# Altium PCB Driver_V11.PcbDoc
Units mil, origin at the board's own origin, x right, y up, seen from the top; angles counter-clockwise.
Board outline 3267.72 x 2755.91 mil, 2 copper layers (TopLayer, BottomLayer); 59 components, 38 nets, 175 pads, 130 vias.
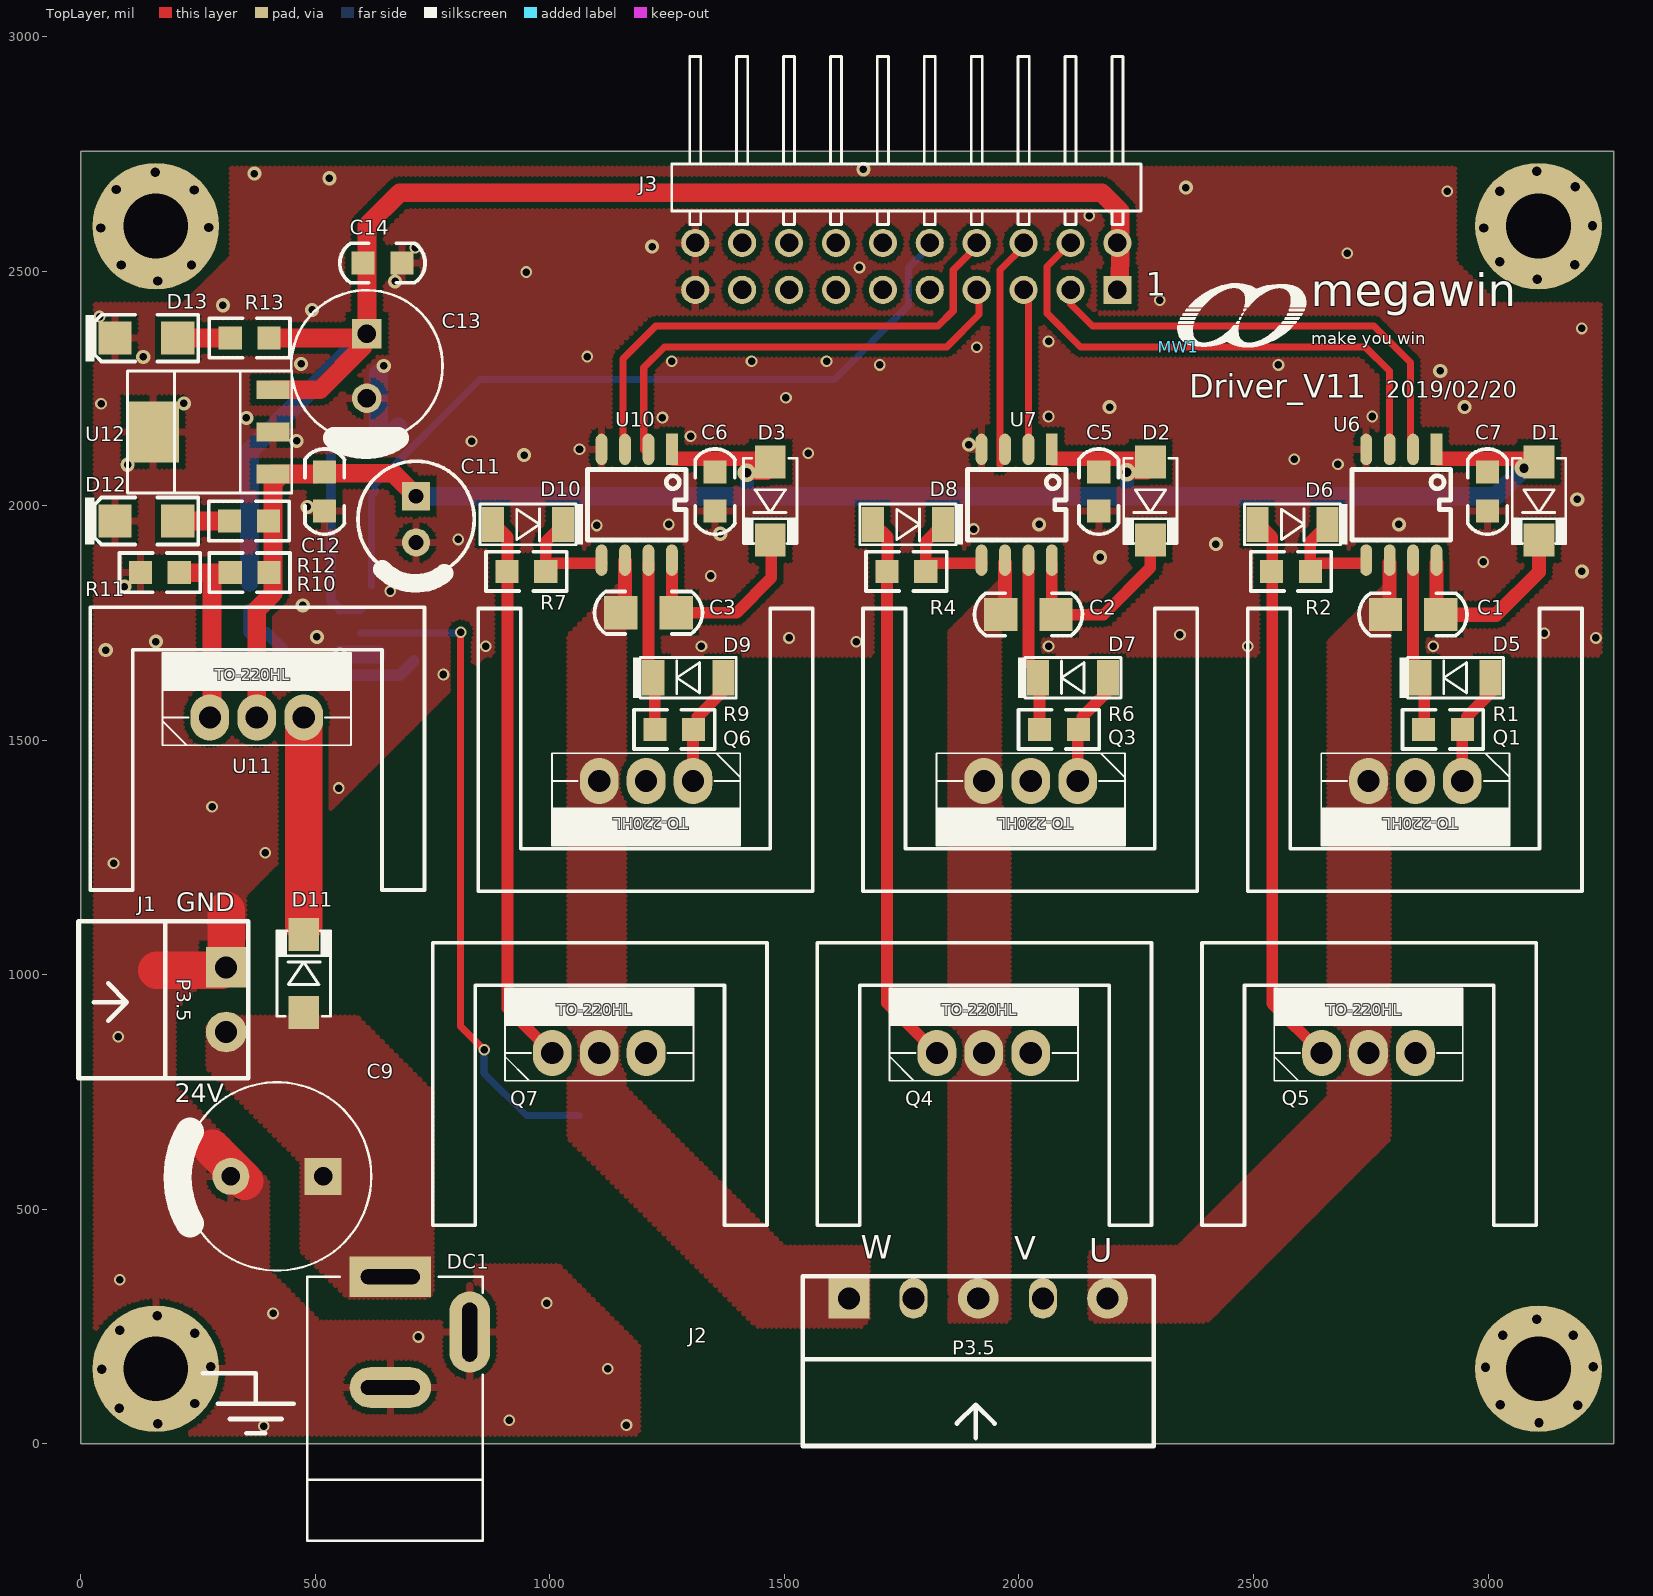
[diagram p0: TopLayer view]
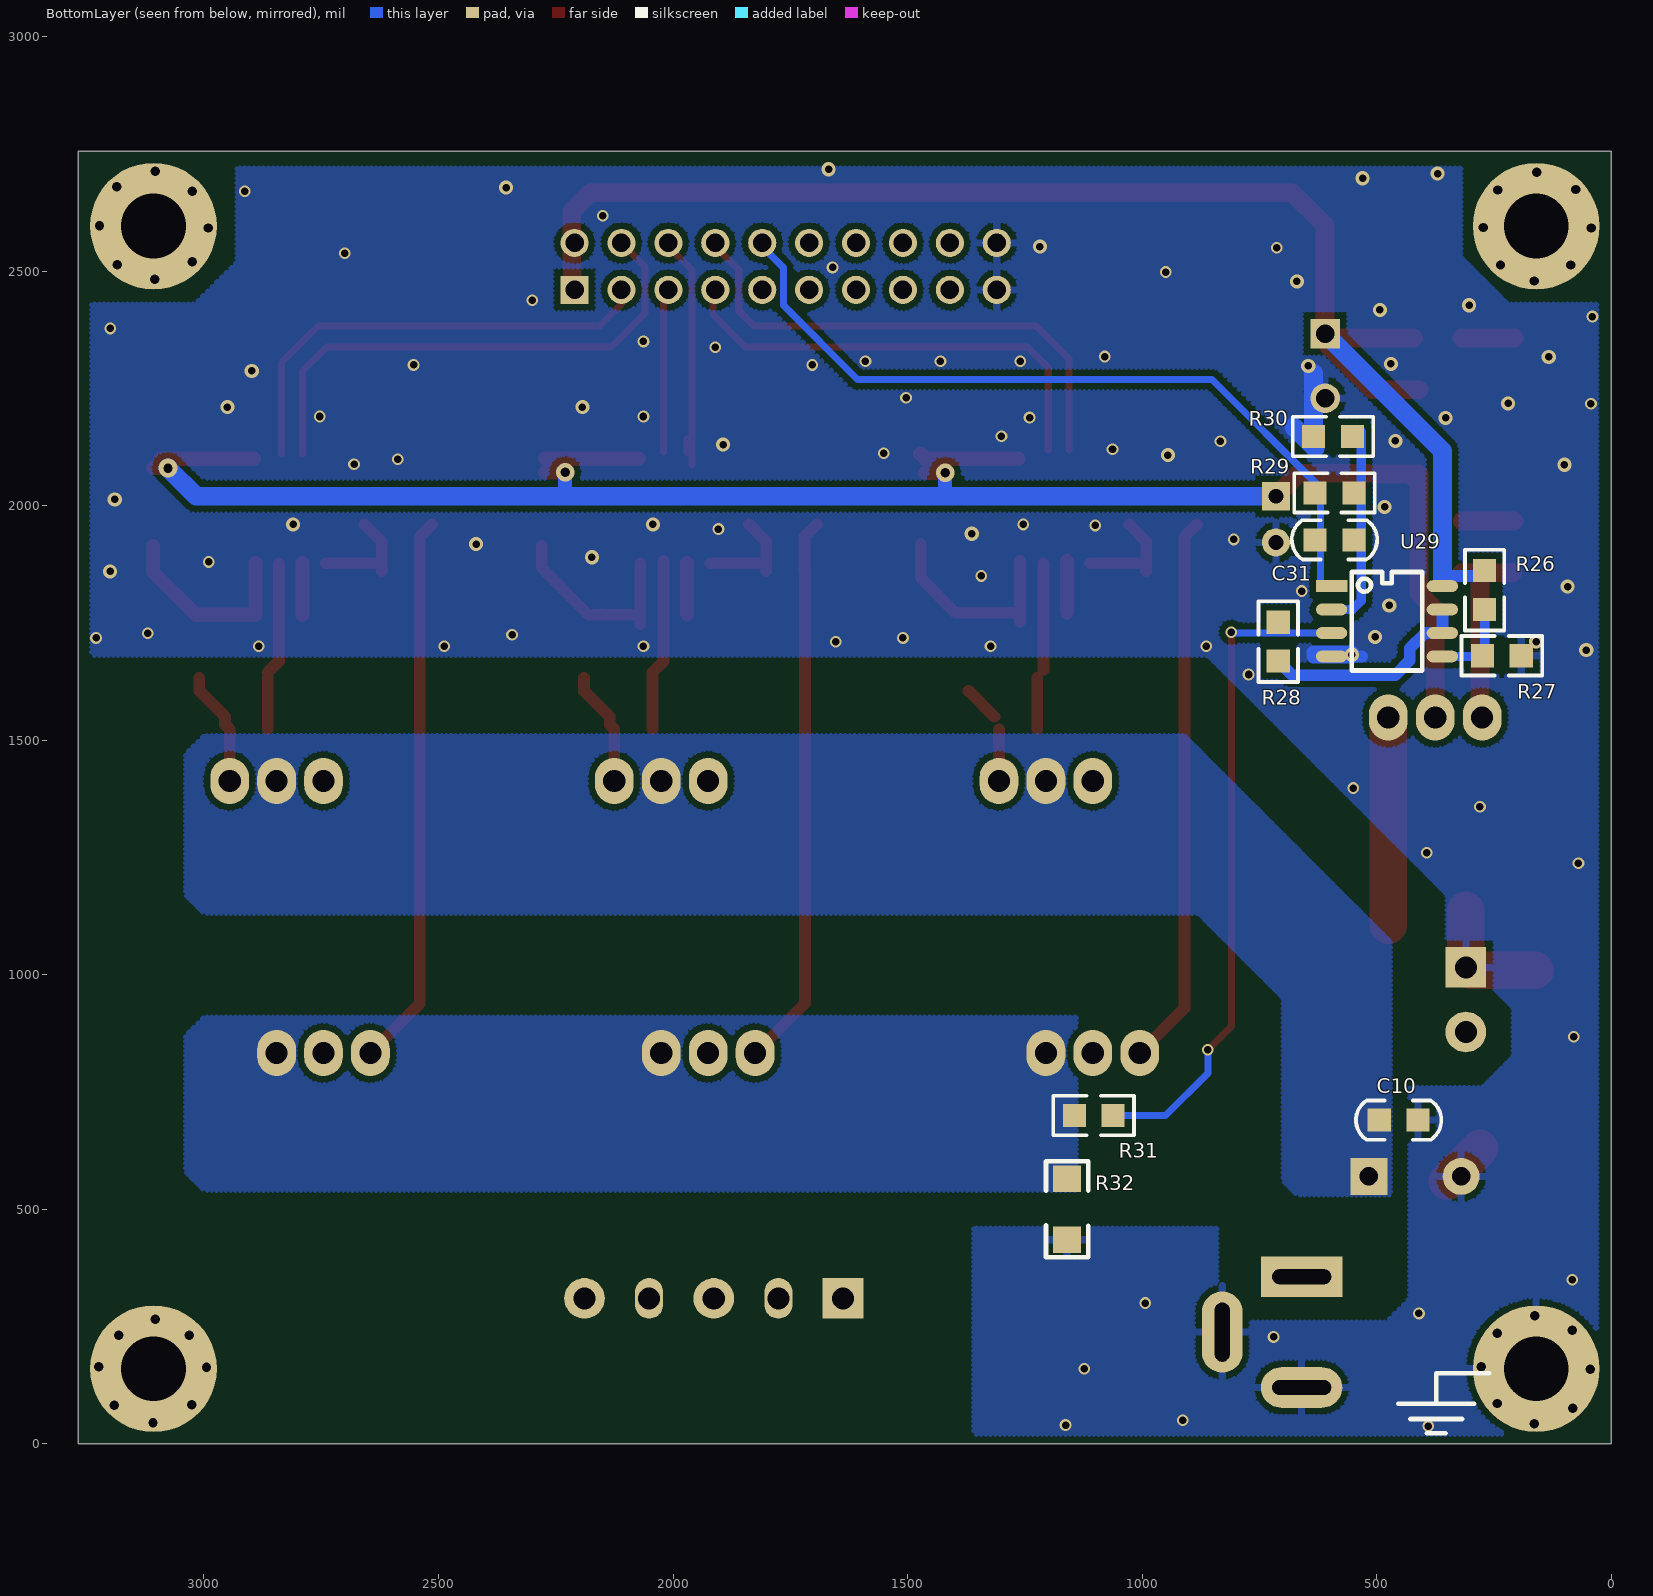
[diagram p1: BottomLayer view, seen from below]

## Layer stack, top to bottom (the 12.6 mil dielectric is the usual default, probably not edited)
TopLayer: signal copper 1.4
Dielectric: dielectric 12.6, FR-4, Dk 4.8
BottomLayer: signal copper 1.4

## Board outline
0,0 0,2755.91 3267.72,2755.91 3267.72,0

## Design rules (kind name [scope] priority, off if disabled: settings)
Clearance 20 [All] p1 off: gap=20
Clearance 13 [All] p2: gap=13
Clearance 6 [All] p3: gap=6
FabricationTestPointUsage TestPointUsage [All] p1: valid=0 allowmultiple=FALSE
FabricationTestpoint Testpoint [All] p1: side=3 testpointundercomponent=TRUE minsize=40 maxsize=100 preferedsize=60 minholesize=20 maxholesize=40 preferedholesize=32 testpointgrid=1 allowsidetop=TRUE allowsidebottom=TRUE usegrid=TRUE gridtolerance=0.01
HoleSize [All] p1: absolutevalues=TRUE maxlimit=500 minlimit=1 maxpercent=80.000 minpercent=20.000
PolygonConnect PWR [InNetClass('PWR')] p1: connectstyle=Direct reliefconductorwidth=10 reliefentries=4 polygonreliefangle="90 Angle"
PolygonConnect VIA [isvia] p2: connectstyle=Direct reliefconductorwidth=10 reliefentries=4 polygonreliefangle="90 Angle"
PolygonConnect PolygonConnect_1 [All] p3: connectstyle=Relief reliefconductorwidth=15 reliefentries=4 polygonreliefangle="90 Angle"
RoutingPriority [All] p1: routingpriority=4
RoutingVias [All] p1: holewidth=16 width=25 viastyle="Through Hole" minholewidth=16 minwidth=24 maxholewidth=28 maxwidth=50
SilkscreenOverComponentPads [All] p1: minsilkscreentomaskgap=10
SolderMaskExpansion [All] p1: expansion=4
Width [All] p1: maxlimit=100 minlimit=8 preferedwidth=10
23 further rules are at their usual default settings.

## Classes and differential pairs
net class pwr: 15V DC+ ICURRENT U V V0 VDD5V W

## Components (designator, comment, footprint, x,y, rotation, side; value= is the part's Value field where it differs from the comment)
C1 "10UF" 1206C 2840.26,1768.15 r180 top
C2 "10UF" 1206C 2020.26,1768.15 r180 top
C3 "10UF" 1206C 1210.26,1771.87 r180 top
C5 "104" 0805C 2170.26,2030 r270 top
C6 "104" 0805C 1352.32,2030 r270 top
C7 "104" 0805C 2998.7,2030 r270 top
C9 "220uF/63V" CEC102P050 418.42,570 r180 top
C10 "0.1u" 0805C 453.26,690 r180 bottom
C11 "47uF/50V" CEC063P025 715,1970.79 r270 top
C12 "0.1u" 0805C 520,2030 r270 top
C13 "220uF/35V" CEC082P035 610,2297.83 r270 top locked
C14 "0.1u" 0805C 643.26,2517.15 r0 top
C31 "2.7n" 0805C 590,1927.15 r0 bottom
D1 "ES1A/SM" DIODE_SMA 3108.7,2010 r270 top
D2 "ES1A/SM" DIODE_SMA 2280.26,2010 r270 top
D3 "ES1A/SM" DIODE_SMA 1470,2010 r270 top
D5 "1N4148" D4148_SMD 2930.46,1633.15 r180 top
D6 "1N4148" D4148_SMD 2583.26,1960 r0 top
D7 "1N4148" D4148_SMD 2115.26,1633.15 r180 top
D8 "1N4148" D4148_SMD 1763.26,1960 r0 top
D9 "1N4148" D4148_SMD 1295.26,1633.15 r180 top
D10 "1N4148" D4148_SMD 953.26,1960 r0 top
D11 "M4" DIODE_SMA 475.26,1002.57 r90 top
D12 "1206" 1206D 140,1967.15 r180 top
D13 "1206" 1206D 140,2357.15 r180 top
DC1 "DC JACK" JACK_DC_0 671.5,241.83 r90 top
J1 "24V / CON2" PW2P3.5_90 310,1015.62 r270 top
J2 "p3.5" PW5P3.5_90 1637.67,310 r0 top
J3 "CON20A" PS10X2P254_90 2210,2460 r180 top locked
MW1 "" MEGAWIN_3.4 2340,2337.83 r0 top
Q1 "IRF520N/TO" TO220HL18X15.3 2945.26,1413.15 r180 top locked
Q3 "IRF520N/TO" TO220HL18X15.3 2125.26,1413.15 r180 top locked
Q4 "IRF520N/TO" TO220HL18X15.3 1825.26,833.15 r0 top locked
Q5 "IRF520N/TO" TO220HL18X15.3 2645.26,833.15 r0 top locked
Q6 "IRF520N/TO" TO220HL18X15.3 1305.26,1413.15 r180 top locked
Q7 "IRF520N/TO" TO220HL18X15.3 1005.26,833.15 r0 top locked
R1 "33" 0805R 2903.92,1523.15 r0 top
R2 "33" 0805R 2580,1860 r180 top
R4 "33" 0805R 1760,1860 r180 top
R6 "33" 0805R 2085.26,1523.15 r0 top
R7 "33" 0805R 950,1860 r180 top
R9 "33" 0805R 1265.26,1523.15 r0 top
R10 "RESISTOR" 0805R 360,1857.15 r180 top
R11 "RESISTOR" 0805R 168.66,1857.15 r180 top
R12 "1K" 0805R 358.66,1967.15 r180 top
R13 "1K" 0805R 360,2357.15 r180 top
R26 "8.2K" 0805R 270,1820 r270 bottom
R27 "1.13K" 0805R 233.26,1680 r180 bottom
R28 "25.5k" 0805R 710,1710 r90 bottom
R29 "25.5k" 0805R 590,2027.15 r0 bottom
R30 "1.0K" 0805R 593.26,2147.15 r0 bottom
R31 "1.0K" 0805R 1103.26,700 r180 bottom
R32 "0.02  (1206)" 1206R 1160,500 r270 bottom
U6 "IR2101S" SO8_150P127 2890.26,2120 r270 top
U7 "IR2101S" SO8_150P127 2070.26,2120 r270 top
U10 "IR2101S" SO8_150P127 1260.26,2120 r270 top
U11 "LM317/TO" TO220HL18X15.3 275.26,1548.15 r0 top locked
U12 "LM78L05  (SOT223)" sot223 410,2067.15 r90 top
U29 "LM358" SO8_150P127 596.22,1828.49 r180 bottom

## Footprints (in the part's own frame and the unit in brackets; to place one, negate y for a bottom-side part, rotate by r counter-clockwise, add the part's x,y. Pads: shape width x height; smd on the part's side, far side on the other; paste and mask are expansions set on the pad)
0805C [mm]
  rect 1.25x1.25 smd: 1(-1.05,0) 2(1.05,0)
  silkscreen extent -2.31,-1.07 2.31,1.07
0805R [mm]
  rect 1.25x1.25 smd: 1(-1.05,0) 2(1.05,0)
  silkscreen extent -2.18,-1.07 2.18,1.07
1206C [mm]
  rect 1.8x1.8 smd: 1(-1.5,0) 2(1.5,0)
  silkscreen extent -2.92,-1.15 2.92,1.16
1206D [mm]
  rect 1.8x1.8 smd: 1(-1.7,0) 2(1.7,0)
  silkscreen extent -2.8,-1.27 3.31,1.28
1206R [mm]
  rect 1.45x1.524 smd: 1(-1.65,0) 2(1.65,0)
  silkscreen extent -2.6,-1.14 2.6,1.14
CEC063P025 [mil]
  rect 60x60 hole 31.5: 1(-49.21,0)
  round 60 hole 31.5: 2(49.21,0)
  silkscreen extent -124,-124 137,124
CEC082P035 [mm]
  rect 1.6x1.6 hole 1: 1(-1.75,0)
  round 1.6 hole 1: 2(1.75,0)
  silkscreen extent -4.1,-4.1 4.45,4.1
CEC102P050 [mm]
  rect 2x2 hole 1: 1(-2.5,0)
  round 2 hole 1: 2(2.5,0)
  silkscreen extent -5.1,-5.1 5.38,5.1
D4148_SMD [mm]
  rect 1.2x1.9 smd: 1(-1.9,0) 2(1.9,0)
  silkscreen extent -2.6,-1.1 3.02,1.1
DIODE_SMA [mil]
  rect 70x65.75 smd: 1(-83,0) 2(83,0)
  silkscreen extent -91,-57 91,57
JACK_DC_0 [mm]
  rect 2.2x4.4 hole 0.8 slot 3.2 at 90 deg: 1(2.905,0.292)
  oval 4.4x2.2 hole 0.8 slot 3.2 at 0 deg: 2(-0.095,-4.008)
  oval 2.2x4.4 hole 0.8 slot 3.2 at 90 deg: 3(-3.095,0.292)
  silkscreen extent -11.39,-4.71 2.91,4.79
MEGAWIN_3.4 [mil]
  silkscreen extent -2,0 272,135
PS10X2P254_90 [mil]
  rect 60x60 hole 39.37: 1(0,0)
  round 60 hole 39.37: 2(0,-100) 3(100,0) 4(100,-100) 5(200,0) 6(200,-100) 7(300,0) 8(300,-100) 9(400,0) 10(400,-100) 11(500,0) 12(500,-100) 13(600,0) 14(600,-100) 15(700,0) 16(700,-100) 17(800,0) 18(800,-100) 19(900,0) 20(900,-100)
  silkscreen extent -50,-498 950,-139
PW2P3.5_90 [mm]
  rect 2.2x2.2 hole 1.2: 1(0,0)
  round 2.2 hole 1.2: 2(3.5,0)
  silkscreen extent -2.5,-8 6,1.2
PW5P3.5_90 [mm]
  rect 2.2x2.2 hole 1.2: 1(0,0)
  oval 1.524x2.2 hole 1.2: 2(3.5,0) 4(10.5,0)
  round 2.2 hole 1.2: 3(7,0) 5(14,0)
  silkscreen extent -2.5,-8 16.5,1.2
SO8_150P127 [mil]
  rect 67x25 smd: 1(0,0)
  oval 67x25 smd: 2(0,-50) 3(0,-100) 4(0,-150) 5(236.22,-150) 6(236.22,-100) 7(236.22,-50) 8(236.22,0)
  silkscreen extent 43,-180 193,30
sot223 [mil]
  rect 40x70 smd: 1(0,0) 2(90,0) 3(180,0)
  rect 129.92x110.24 smd: 2(90,255.91)
  silkscreen extent -40,-40 220,310
TO220HL18X15.3 [mm]
  oval 2.1x2.5 hole 1.2: 1(0,0) 2(2.54,0) 3(5.08,0)
  silkscreen extent -6.48,-9.33 11.62,5.97

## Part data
C1 C2 C3 C9 C11 C13: library part CAP
C5 C6 C7 C10 C12 C14 C31: library part "CAP NP"
D11: library part DIODE
D12 D13: library part LED_SC
DC1: library part JACK_DC2
J1: library part CON2
J2: library part CON5
R1 R2 R4 R6 R7 R9 R12 R13 R26 R27 R28 R29 R30 R31 R32: library part RESISTOR
U12: library part LM78L05

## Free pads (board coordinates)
  round 270 hole 138: 1(160,160) 1(160,2595.91) 1(3107.72,160) 1(3107.72,2595.91)

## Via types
v1: diameter 25, hole 16, TopLayer to BottomLayer, tented both sides, 61 vias
v2: diameter 30, hole 16, TopLayer to BottomLayer, tented both sides, 34 vias
v3: diameter 30, hole 20, TopLayer to BottomLayer, tented both sides, 32 vias
v4: diameter 40, hole 20, TopLayer to BottomLayer, tented both sides, 3 vias

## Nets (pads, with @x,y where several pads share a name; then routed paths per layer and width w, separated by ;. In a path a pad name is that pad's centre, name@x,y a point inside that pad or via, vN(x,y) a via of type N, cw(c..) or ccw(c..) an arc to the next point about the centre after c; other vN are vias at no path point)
15V: C5.1 C6.1 C7.1 C11.1 C12.1 D1.1 D2.1 D3.1 R10.1 R12.1 U6.1 U7.1 U10.1 U11.2 U12.1 | length 4047.7
  TopLayer w30: U10.1@1263.26,2100 D3.1@1463.26,2100 ; v4(1420,2070) D3.1@1463.26,2070 ; D3.1@1470,2110 D3.1@1473.26,2110 ; U7.1@2073.26,2100 D2.1@2273.26,2100 ; v4(2230,2071) D2.1@2273.26,2071 ; U6.1@2893.26,2100 D1.1@3093.26,2100 ; v4(3076.74,2080) D1.1@3108.7,2080
  TopLayer w40: U11.2 375.26,1778.41 410,1813.15 U12.1 ; U12.1@420,2057.15 U12.1 ; C12.1@500,2067.15 U12.1 ; C12.1@520,2069.16 665.84,2069.16 C11.1
  BottomLayer w30: 1420,2026.74 v4(1420,2070) ; 2230,2027.74 v4(2230,2071)
  BottomLayer w40: C11.1 3016.74,2020 v4(3076.74,2080)
DC+: C9.1 C10.1 D11.1 DC1.1 J1.2 Q1.2 Q3.2 Q6.2
FAULT: C31.2 J3.10 R29.2 U29.1 | length 1644.8
  BottomLayer w15: U29.1@620,1828.49 R29.2@620,2017.15 ; R29.2@624.66,2042.49 850.8,2268.62 1606.47,2268.62 1765,2427.15 1765,2507.15 J3.10@1815,2557.15
  BottomLayer w20: R29.2@623.26,2027.15 623.26,2027.84 R29.2@626.73,2031.51
GND: C5.2 C6.2 C7.2 C9.2 C10.2 C11.2 C12.2 C13.2 C14.2 D12.2 D13.2 DC1.2 DC1.3 J1.1 J3.19 J3.20 pad.1@160,160 R11.2 R27.2 R30.2 R32.2 U6.4 U7.4 U10.4 U12.2 U29.4 | length 759.2
  TopLayer w80: 162.17,1010 J1.1@300,1010 ; 280,630 330,580 C9.2@350,560 ; J1.1 310,1137.83
  BottomLayer w25: 531.22,1678.49 v2@553.11,1678.49 ; U29.4@620,1678.49 635,1678.49
  BottomLayer w30: v2@553.11,1678.49 U29.4 635,1678.49 ; v2@553.11,1687.15 596.22,1687.15 635,1687.15
  BottomLayer w40: 631.34,2122.42 645.33,2136.42 676.74,2167.83 ; R30.2 634.6,2228.93 634.6,2282.42
  other v1: 390,37.83 1163.26,40 913.26,50 1123.26,160 720,227.83 410,277.83 993.26,300 83.26,350 80,867.83 70,1237.83 393.26,1260 280,1357.83 550,1397.83 773.26,1640 863.26,1700 1323.26,1700 2063.26,1700 2487.66,1700 2883.26,1700 1653.26,1710 1510,1717.83 3230,1717.83 2343.26,1725 3120,1727.83 660,1817.83 1343.26,1850 2990,1880 805,1927.83 1903.26,1950 1100,1957.83 1253.26,1960 2680.2,2088.15 2586.94,2098.82 1551.06,2111.77 1063.26,2120 833.26,2137.15 1300,2147.83 1240,2187.83 2063.26,2190 2753.26,2190 43.26,2217.15 1503.26,2230 1703.26,2300 2553.26,2300 1260,2307.83 1430,2307.83 1590,2307.83 1080,2317.83 1910,2337.83 2063.26,2350 3200,2377.83 40.12,2402.94 2300,2437.83 950,2497.83 1660,2507.83 2700,2537.83 713.26,2550 2150,2617.83 2913.26,2670
  other v2: 553.11,1682.15 53.26,1692.15 160,1710 503.26,1720 473.26,1787.15 93.26,1827.15 3200,1860 2173.26,1890 2420,1917.83 1363.26,1940 2043.26,1960 2810,1960 483.26,1997.15 3190.2,2013.15 100,2087.15 945,2107.83 1893.26,2130 460,2137.83 353.26,2187.15 2193.26,2210 2950,2210 220,2217.83 2898.26,2287.15 646,2297.83 470,2302.15 133.26,2317.15 493.26,2417.15 303.26,2427.15 670,2477.83 1218.26,2552.15 2356,2677.83 530,2697.83 370,2707.83 1668.26,2717.15
  other v3: 164,43 82,76 243,86 45,159 277,164 243,236 83,242 163,273
ICURRENT: Q4.3 Q5.3 Q7.3 R31.1 R32.1
NetC1_1: C1.1 D1.2 U6.8 | length 422
  TopLayer w30: U6.8@2890.26,1877.37 2890.26,1767.37 3017.43,1767.37 3108.7,1858.64 D1.2@3108.7,1914.37
NetC2_1: C2.1 D2.2 U7.8 | length 419
  TopLayer w25: C2.1@2070.26,1747.7 C2.1@2070.26,1767.37 ; C2.1@2070.26,1768.15 U7.8@2070.26,1877.37 ; C2.1@2079.32,1767.37 2150.26,1767.37 ; 2150.26,1768.15 2150.26,1767.37 ; D2.2@2280.26,1914.37 2280.26,1867.37 2180.26,1767.37 2150.26,1767.37
NetC3_1: C3.1 D3.2 U10.8 | length 514.5
  TopLayer w25: C3.1@1260.26,1752.2 C3.1@1260.26,1771.87 ; 1260.26,1841.87 C3.1@1260.26,1771.87 ; U10.8@1260.26,1881.87 C3.1@1260.26,1771.87 ; D3.2@1472.32,1918.09 1472.32,1846.09 1398.09,1771.87 C3.1 C3.1@1260.26,1771.87
NetC31_1: C31.1 R29.1 R30.1 U29.2 | length 431.6
  BottomLayer w20: R30.1@533.26,2157.83 533.26,1797.15 552.44,1777.97 ; 552.44,1778.49 U29.2
NetD5_1: D5.1 Q1.1 R1.2 | length 246.8
  TopLayer w25: Q1.1 R1.2 2955,1532.89 2955,1550 3010,1605 3010,1620 3010.06,1620.06 D5.1@3010.06,1633.15
NetD5_2: D5.2 R1.1 U6.7 | length 352.7
  TopLayer w25: U6.7@2840.26,1877.37 2840.26,1668.15 D5.2@2863.92,1644.49 ; R1.1@2863.92,1523.15 D5.2@2863.92,1633.15
NetD6_1: D6.1 Q5.1 R2.2 | length 1181.5
  TopLayer w25: D6.1@2513.26,1960 2540,1933.26 2540,938.41 Q5.1
NetD6_2: D6.2 R2.1 U6.5 | length 216.8
  TopLayer w25: R2.1 2621.34,1923.28 D6.2 ; R2.1@2638.71,1877.37 U6.5@2740.26,1877.37
NetD7_1: D7.1 Q3.1 R6.2 | length 246.8
  TopLayer w25: Q3.1 2125.26,1523.15 2135,1532.89 2135,1550 2190,1605 2190,1620 2190.06,1620.06 D7.1
NetD7_2: D7.2 R6.1 U7.7 | length 368.5
  TopLayer w25: U7.7@2020.26,1881.87 2020.26,1668.15 2043.92,1644.49 R6.1
NetD8_1: D8.1 Q4.1 R4.2 | length 1182.1
  TopLayer w25: D8.1@1693.26,1960 1720,1933.26 R4.2@1720,1860 ; R4.2 1718.66,939.75 Q4.1
NetD8_2: D8.2 R4.1 U7.5 | length 216.8
  TopLayer w25: R4.1 1801.34,1923.28 D8.2 ; R4.1@1818.71,1877.37 U7.5@1920.26,1877.37
NetD9_1: D9.1 Q6.1 R9.2 | length 187.8
  TopLayer w25: Q6.1 R9.2@1305.26,1523.15 ; 1315,1550 D9.1@1370,1605
NetD9_2: D9.2 R9.1 U10.7 | length 337.1
  TopLayer w25: D9.2@1210.26,1650.26 U10.7@1210.26,1877.37 ; R9.1 D9.2@1223.92,1633.15
NetD10_1: D10.1 Q7.1 R7.2 | length 1198.2
  TopLayer w25: D10.1@883.26,1960 910,1933.26 910,928.41 Q7.1 Q7.1@1020,818.41
NetD10_2: D10.2 R7.1 U10.5 | length 216.8
  TopLayer w25: R7.1 991.34,1923.28 D10.2 ; R7.1@1008.71,1877.37 U10.5@1110.26,1877.37
NetD11_2: D11.2 U11.3 | length 442.6
  TopLayer w80: D11.2@475.26,1105.57 U11.3
NetD12_1: D12.1 R12.2 | length 110.4
  TopLayer w40: D12.1 R12.2
NetD13_1: D13.1 R13.2 | length 111.7
  TopLayer w40: D13.1 R13.2
NetJ3_3: J3.3 U6.2 | length 1001.7
  TopLayer w15: J3.3 2110,2430 2156.85,2383.15 2756.85,2383.15 2834.72,2305.28 U6.2@2834.72,2110
NetJ3_4: J3.4 U6.3 | length 1128.5
  TopLayer w15: J3.4 2060,2510 2060,2410 2131.57,2338.43 2738.33,2338.43 2790,2286.76 U6.3@2790,2110
NetJ3_5: J3.5 U7.2 | length 343.6
  TopLayer w15: U7.2@2020,2113.59 J3.5@2020,2457.15
NetJ3_6: J3.6 U7.3 | length 552.3
  TopLayer w15: 1960,2086.44 1960,2450 ; 1960,2480 1960,2450 ; U7.3@1970.26,2113.59 U7.3 U7.3@1970.26,2142.37 ; J3.6@2015,2557.15 1960,2502.15 1960,2450
NetJ3_7: J3.7 U10.2 | length 987.8
  TopLayer w15: U10.2@1200.26,2118.09 1200.26,2294.43 1244.27,2338.43 1846.28,2338.43 1915,2407.15 J3.7@1915,2457.15
NetJ3_8: J3.8 U10.3 | length 1106.3
  TopLayer w15: U10.3@1155.54,2118.09 1155.54,2312.95 1225.74,2383.15 1827.76,2383.15 1860,2415.39 1860,2502.15 J3.8@1915,2557.15
NetR10_2: R10.2 R11.1 U11.1 | length 417.7
  TopLayer w40: R11.1 280,1857.15 ; U11.1@280,1548.15 280,1857.15 ; R10.2 280,1857.15
NetR26_2: R26.2 R27.1 U29.5 | length 168.8
  BottomLayer w20: R27.1@270,1678.49 U29.5 ; R27.1@270,1699.83 R26.2
NetR28_2: R28.2 R31.2 U29.3 | length 1415.7
  TopLayer w15: v1(810,1730) 810,890 v1(860,840)
  BottomLayer w15: U29.3 808.49,1728.49 v1(810,1730) ; v1(860,840) 860,790 950,700 R31.2 R31.2@1063.26,700
U: C1.2 J2.5 Q1.3 Q5.2 U6.6 | length 110
  TopLayer w30: C1.2@2790.26,1767.37 U6.6@2790.26,1877.37
V: C2.2 J2.3 Q3.3 Q4.2 U7.6 | length 109.2
  TopLayer w30: C2.2@1970.26,1768.15 U7.6@1970.26,1877.37
V0: R28.1 U29.6 U29.7 | length 464.8
  BottomLayer w25: U29.7 U29.6 396.77,1728.49 429.43,1695.83 429.43,1670 460.76,1638.67 680,1638.67 R28.1
VDD5V: C13.1 C14.1 J3.1 J3.2 R13.1 R26.1 U12.3 U29.8 | length 3273.6
  TopLayer w40: U12.3 510,2247.15 600.43,2337.58 C13.1@600.43,2357.15 ; R13.1@421.34,2357.15 C13.1@600.43,2357.15 ; C13.1@613.26,2357.15 C13.1@600.43,2357.15 ; 1225,2667.15 1280,2667.15 ; J3.1@2215,2457.15 2215.04,2459.94 2216.26,2557.13 2216.26,2627.7 2176.81,2667.15 1280,2667.15 ; C13.1@600.43,2357.15 C13.1 610,2597.15 680,2667.15 1280,2667.15
  BottomLayer w25: R26.1@280,1850 360,1850
  BottomLayer w40: U29.8@360,1837.15 360,1850 360,2116.72 C13.1
W: C3.2 J2.1 Q6.3 Q7.2 U10.6 | length 110
  TopLayer w30: C3.2@1160.26,1771.87 U10.6@1160.26,1881.87
pads on no net: J2.2 J2.4 J3.9 J3.11 J3.12 J3.13 J3.14 J3.15 J3.16 J3.17 J3.18
copper on no net:
  other v3: 3108.72,45 3191.72,82 3025.72,83 2994.72,163 3224.72,164 3031.72,231.78 3181.72,231.78 3103.72,265.78 164,2478.91 3104.72,2482.91 86,2512.91 236,2512.91 3184.72,2513.91 3024.72,2519.91 43,2591.91 2990.72,2591.91 273,2592.91 3222.72,2596.91 3024.72,2669.91 242,2672.91 76,2673.91 3185.72,2679.91 159,2710.91 3103.72,2712.91

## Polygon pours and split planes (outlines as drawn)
GND on TopLayer "Top Layer-No Net" (hatched 90Degree grid 10 track 10, remove dead copper, pour order 1005): 1190,20 30,20 30,1250 350,1250 350,980 255,980 200,925 200,762.95 400,559.26 400,370 510,260 840,260 840,380 1020,380 1190,210
U on TopLayer "Top Layer-No Net" (hatched 90Degree grid 10 track 10, remove dead copper, pour order 1002): 2790.26,1840 2750,1800 2660,1710 2660,740 2340,420 2165,420 2150,405 2150,270 2160,260 2400,260 2790.26,650.26
W on TopLayer "Top Layer-No Net" (hatched 90Degree grid 10 track 10, remove dead copper, pour order 1002): 1040,650 1440,250 1665,250 1680,265 1680,410 1670,420 1500,420 1160.03,759.97 1160.26,1844.5 1120,1804.5 1040,1724.5 1040,1633.83 1040,934.5
GND on TopLayer "Top Layer-No Net" (hatched 90Degree grid 10 track 10, remove dead copper, pour order 1009): 3240,1680 859.95,1680 339.34,1159.68 30,1160.61 30,2430 220.02,2430 320,2529.82 320,2720 2930,2720 2930,2519.87 3020.02,2430 3240,2430
DC+ on TopLayer "Top Layer-No Net" (hatched 90Degree grid 10 track 10, remove dead copper, pour order 1003): 750.05,749.95 750.26,321.76 740,311.5 568.5,311.5 470,410 470,600 270,800 270,890 290,910 590,910
V on TopLayer "Top Layer-No Net" (hatched 90Degree grid 10 track 10, remove dead copper, pour order 1001): 1970.26,1850 1852.06,1732.06 1852.06,260 1980,260 1980,1341.38 1960,1361.38 1960,1740.1 1970,1740
GND on BottomLayer "Top Layer-No Net" (hatched 90Degree grid 10 track 10, remove dead copper, pour order 1000): 1360,460 1360,20 30,20 30,1187.83 350,1187.83 350,975 255,975 210,930 210,825 275,760 430,760 430,310 480,260 770,260 840,330 840,460
DC+ on BottomLayer "Top Layer-No Net" (hatched 90Degree grid 10 track 10, remove dead copper, pour order 1006): 3000,1510 3040,1470 3040,1170 3000,1130 880,1130 700,950 700,560 670,530 470,530 470,1070 910,1510
ICURRENT on BottomLayer "Top Layer-No Net" (hatched 90Degree grid 10 track 10, remove dead copper, pour order 1007): 1140,910 3000,910 3040,870 3040,580 3000,540 1140,540
GND on BottomLayer "Top Layer-No Net" (hatched 90Degree grid 10 track 10, remove dead copper, pour order 1009): 3240,1680 859.95,1680 339.34,1159.68 30,1160.61 30,2430 220.02,2430 320,2529.82 320,2720 2930,2720 2930,2519.87 3020.02,2430 3240,2430

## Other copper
BottomLayer:
  region net GND: 254.26,139.26 254.26,246 94.94,246 94.94,139.26

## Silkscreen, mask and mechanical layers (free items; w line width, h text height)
TopOverlay:
  lines w10: 260,150.5 373.26,150.5 373.26,85.65 ; 292.17,85.65 454.26,85.65 ; 318.26,52.83 428.26,52.83 ; 353.26,22.83 393.26,22.83
  text "1" at 2270,2447.83 h50
  text "Driver_V11" at 2363.26,2230 h50
  text "2019/02/20" at 2783.26,2230 h35
  text "GND" at 203.26,1135 h40
  text "24V" at 200,727.83 h40
  text "W" at 1663.26,395 h50
  text "V" at 1990,392.67 h50
  text "U" at 2150,387.83 h50
BottomOverlay:
  lines w10: 260,150.5 373.26,150.5 373.26,85.65 ; 292.17,85.65 454.26,85.65 ; 318.26,52.83 428.26,52.83 ; 353.26,22.83 393.26,22.83
TopSolder:
  lines w80: 502.61,214.57 735,214.57 ; 520,57.83 520,192.39
  lines w100: 1090,927.83 1090,1707.83 ; 1910,927.83 1910,1707.83 ; 2730,927.83 2730,1707.83
  lines w120: 1913.26,380 1913.26,710 ; 2723.26,691.09 2723.26,720
  lines w150: 105,1240 105,542.83 460,187.83 ; 422.17,770 488.26,770 653.26,605 653.26,460 ; 1125.43,687.83 1447.72,365.54 ; 1474.57,337.83 1590,337.83 ; 2270,347.83 2380,347.83 2723.26,691.09
BottomSolder:
  region: 523.26,1110 523.26,630 683.26,630 683.26,1110
  rectangle: 1200,540 2993.26,757.83
  region: 642.72,930.54 1062.72,1350.54 918.26,1495 498.26,1075
  region: 3013.26,1340 823.26,1340 823.26,1137.83 3013.26,1137.83
  region: 1143.94,456.74 1143.94,360 1353.26,360 1353.26,456.74
  rectangle: 1395.62,1280 1853.26,1485
  rectangle: 2213.26,1285 2670.9,1490
  rectangle: 2113.26,705 2570.9,910
  rectangle: 1295.62,700 1753.26,905
  lines w120: 130,507.83 480,157.83
  lines w200: 130,420 130,1357.83
Mechanical1:
  the board outline again, w8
